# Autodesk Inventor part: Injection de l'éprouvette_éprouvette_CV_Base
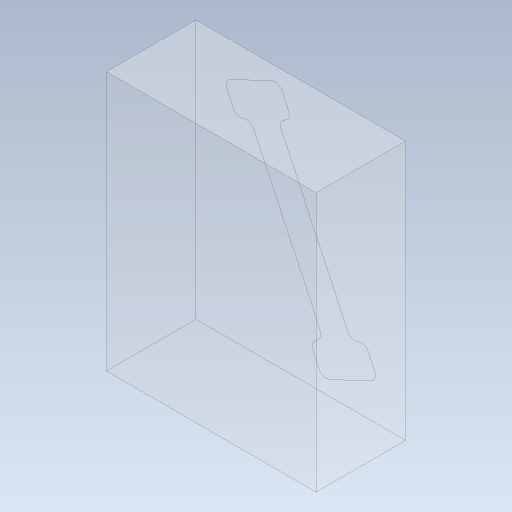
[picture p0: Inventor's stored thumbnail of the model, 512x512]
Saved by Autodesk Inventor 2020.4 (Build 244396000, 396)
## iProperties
Created: 2021-10
Part Number: Injection de l'éprouvette_éprouvette_CV_Base
Material: Générique
Document SubType Name: Modeling
Designer: mel
Density: 1 g/cm^3
Appearance: Par défaut
Author: mel
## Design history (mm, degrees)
node "Injection de l'éprouvette_éprouvette_MP"
feature "Solide4::Injection de l'éprouvette_éprouvette_MP"
tag "FonctionRepérage1"
node "Solide1"
feature "Injection de l'éprouvette_éprouvette_MP_Corps"
